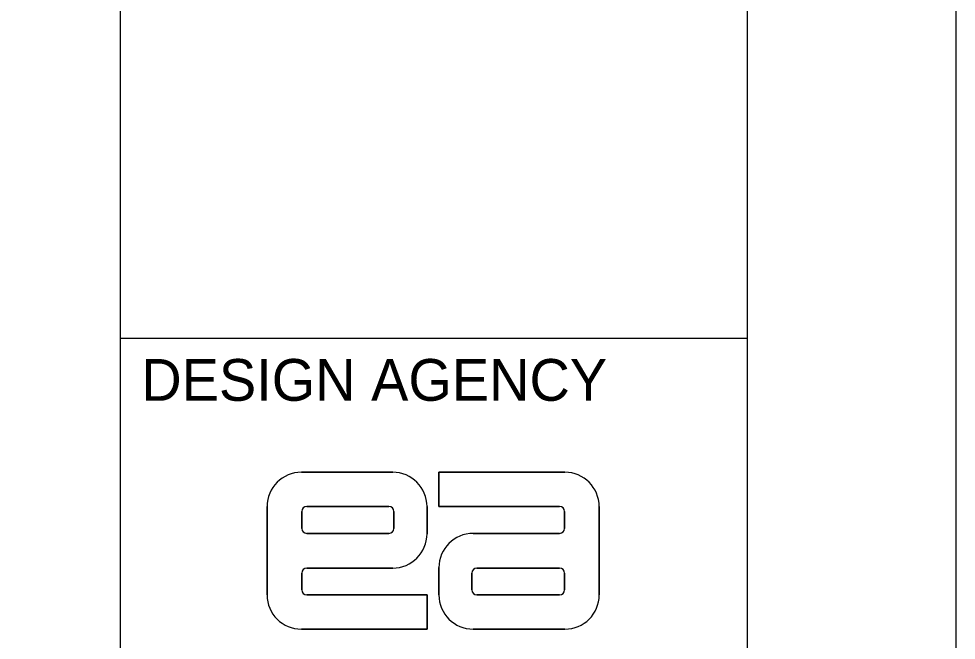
# Model space of a CAD drawing. Extents: x 0 to 34, y 0 to 22.
# Drawn here: x 31.757 to 34, y 3.777 to 5.265 of the extents above; entities that cross this region are included whole.
import ezdxf

# ---------------------------------------------------------------- set-up
doc = ezdxf.new("R2010")
doc.units = 0
for name, color, linetype in [('SH_Border', 7, 'Continuous'), ('SH_Cut_Line', 7, 'Continuous'), ('SH_Data', 7, 'Continuous'), ('TX_X_20', 7, 'Continuous')]:
    doc.layers.add(name, color=color, linetype=linetype)

msp = doc.modelspace()

# ---------------------------------------------------------------- linework, layer by layer
at = {"layer": 'SH_Border'}
for p, q in [((32, 0.5), (32, 21.5)), ((32, 4.5), (33.5, 4.5))]:
    msp.add_line(p, q, dxfattribs=at)
msp.add_lwpolyline([(1.5, 21.5), (33.5, 21.5), (33.5, 0.5), (1.5, 0.5)], close=True, dxfattribs=at)
at = {"layer": 'SH_Cut_Line'}
msp.add_lwpolyline([(0, 0), (34, 0), (34, 22), (0, 22)], close=True, dxfattribs=at)
at = {"layer": 'TX_X_20'}
for p, q in [((32.6515, 4.1788), (32.433, 4.1788)), ((32.433, 4.1788), (32.6515, 4.1788)), ((32.762, 4.1788), (33.0635, 4.1788)), ((32.762, 4.0967), (32.762, 4.1788)), ((32.351, 4.0967), (32.351, 3.8852)), ((32.351, 3.8852), (32.351, 4.0967)), ((32.434, 4.0444), (32.434, 4.0849)), ((32.434, 4.0849), (32.434, 4.0444)), ((32.4459, 4.0967), (32.6426, 4.0967)), ((32.6426, 4.0967), (32.4459, 4.0967)), ((32.6545, 4.0849), (32.6545, 4.0444)), ((32.6545, 4.0444), (32.6545, 4.0849)), ((32.7336, 4.0315), (32.7336, 4.0967)), ((32.7336, 4.0967), (32.7336, 4.0315)), ((33.0507, 4.0967), (32.762, 4.0967)), ((33.0626, 4.0849), (33.0626, 4.0444)), ((33.0626, 4.0444), (33.0626, 4.0849)), ((33.1456, 3.8852), (33.1456, 4.0967)), ((33.1456, 4.0967), (33.1456, 3.8852)), ((32.6426, 4.0325), (32.4459, 4.0325)), ((32.4459, 4.0325), (32.6426, 4.0325)), ((33.0507, 4.0325), (32.8441, 4.0325)), ((32.8441, 4.0325), (33.0507, 4.0325)), ((32.4459, 3.9494), (32.6515, 3.9494)), ((32.6515, 3.9494), (32.4459, 3.9494)), ((32.762, 3.9504), (32.762, 3.8852)), ((32.762, 3.8852), (32.762, 3.9504)), ((32.853, 3.9494), (33.0507, 3.9494)), ((33.0507, 3.9494), (32.853, 3.9494)), ((32.434, 3.8971), (32.434, 3.9376)), ((32.434, 3.9376), (32.434, 3.8971)), ((32.8411, 3.8971), (32.8411, 3.9376)), ((32.8411, 3.9376), (32.8411, 3.8971)), ((33.0626, 3.9376), (33.0626, 3.8971)), ((33.0626, 3.8971), (33.0626, 3.9376)), ((32.4459, 3.8852), (32.7336, 3.8852)), ((32.7336, 3.8852), (32.7336, 3.8031)), ((33.0507, 3.8852), (32.853, 3.8852)), ((32.853, 3.8852), (33.0507, 3.8852)), ((32.7336, 3.8031), (32.433, 3.8031)), ((32.8441, 3.8031), (33.0635, 3.8031)), ((33.0635, 3.8031), (32.8441, 3.8031))]:
    msp.add_line(p, q, dxfattribs=at)
for points in [[(33.0635, 4.1788), (32.762, 4.1788), (32.762, 4.0967), (33.0507, 4.0967)], [(32.433, 3.8031), (32.7336, 3.8031), (32.7336, 3.8852), (32.4459, 3.8852)]]:
    msp.add_lwpolyline(points, dxfattribs=at)
for centre, radius, start, end in [((32.433, 4.0967), 0.0821, 90, 180), ((32.433, 4.0967), 0.0821, 90, 180), ((32.6515, 4.0967), 0.0821, 0, 90), ((32.6515, 4.0967), 0.0821, 0, 90), ((33.0635, 4.0967), 0.0821, 0, 90), ((33.0635, 4.0967), 0.0821, 0, 90), ((32.4459, 4.0849), 0.0119, 90, 180), ((32.4459, 4.0849), 0.0119, 90, 180), ((32.6426, 4.0849), 0.0119, 0, 90), ((32.6426, 4.0849), 0.0119, 0, 90), ((33.0507, 4.0849), 0.0119, 0, 90), ((33.0507, 4.0849), 0.0119, 0, 90), ((32.4459, 4.0444), 0.0119, 180, 270), ((32.4459, 4.0444), 0.0119, 180, 270), ((32.6426, 4.0444), 0.0119, 270, 0), ((32.6426, 4.0444), 0.0119, 270, 0), ((33.0507, 4.0444), 0.0119, 270, 0), ((33.0507, 4.0444), 0.0119, 270, 0), ((32.6515, 4.0315), 0.0821, 270, 360), ((32.6515, 4.0315), 0.0821, 270, 360), ((32.8441, 3.9504), 0.0821, 90, 180), ((32.8441, 3.9504), 0.0821, 90, 180), ((32.4459, 3.9376), 0.0119, 90, 180), ((32.4459, 3.9376), 0.0119, 90, 180), ((32.853, 3.9376), 0.0119, 90, 180), ((32.853, 3.9376), 0.0119, 90, 180), ((33.0507, 3.9376), 0.0119, 0, 90), ((33.0507, 3.9376), 0.0119, 0, 90), ((32.433, 3.8852), 0.0821, 180, 270), ((32.433, 3.8852), 0.0821, 180, 270), ((32.4459, 3.8971), 0.0119, 180, 270), ((32.4459, 3.8971), 0.0119, 180, 270), ((32.8441, 3.8852), 0.0821, 180, 270), ((32.8441, 3.8852), 0.0821, 180, 270), ((32.853, 3.8971), 0.0119, 180, 270), ((32.853, 3.8971), 0.0119, 180, 270), ((33.0507, 3.8971), 0.0119, 270, 0), ((33.0507, 3.8971), 0.0119, 270, 0), ((33.0635, 3.8852), 0.0821, 270, 360), ((33.0635, 3.8852), 0.0821, 270, 360)]:
    msp.add_arc(centre, radius, start, end, dxfattribs=at)

# ---------------------------------------------------------------- texts
at = {"layer": 'SH_Data'}
msp.add_text('DESIGN AGENCY', height=0.1, dxfattribs=at).set_placement((32.05, 4.35))

doc.saveas('drawing.dxf')
